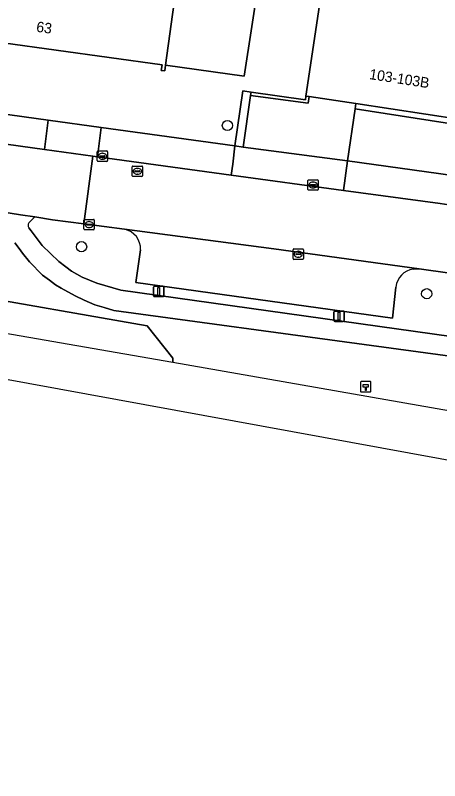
# Model space of a CAD drawing. Extents: x 163008 to 163854, y 382777 to 383982.
# Drawn here: x 163332.7 to 163373.4, y 382797.9 to 382871.4 of the extents above; entities that cross this region are included whole.
import ezdxf

# ---------------------------------------------------------------- set-up
doc = ezdxf.new("R2010")
doc.units = 0
for name, color, linetype in [('IMGEO_Boom', 7, 'Continuous'), ('IMGEO_Erf', 7, 'Continuous'), ('IMGEO_Fietspad_open', 7, 'Continuous'), ('IMGEO_Groenvoorziening', 7, 'Continuous'), ('IMGEO_Hectometerpaal', 7, 'Continuous'), ('IMGEO_Hek', 7, 'Continuous'), ('IMGEO_Kolk', 7, 'Continuous'), ('IMGEO_Lichtmast', 7, 'Continuous'), ('IMGEO_Muur', 7, 'Continuous'), ('IMGEO_Pand', 7, 'Continuous'), ('IMGEO_Pand_nummerreeks', 7, 'Continuous'), ('IMGEO_Parkeervlak_gesloten', 7, 'Continuous'), ('IMGEO_Parkeervlak_open', 7, 'Continuous'), ('IMGEO_Rijbaan_lokaal_open', 7, 'Continuous'), ('IMGEO_Rioolput', 7, 'Continuous'), ('IMGEO_Voetpad_gesloten', 7, 'Continuous'), ('IMGEO_Voetpad_open', 7, 'Continuous'), ('IMGEO_Waterloop', 7, 'Continuous')]:
    doc.layers.add(name, color=color, linetype=linetype)

msp = doc.modelspace()

# ---------------------------------------------------------------- linework, layer by layer
at = {"layer": 'IMGEO_Boom'}
for centre in [(163353.055, 382860.785), (163339.071, 382849.16), (163372.178, 382844.649)]:
    msp.add_circle(centre, 0.489, dxfattribs=at)
at = {"layer": 'IMGEO_Erf'}
for points in [[(163280.455, 382868.905), (163293.729, 382867.082), (163293.904, 382867.058), (163299.016, 382866.356), (163304.629, 382865.585), (163304.8, 382865.562), (163309.55, 382864.924), (163309.567, 382864.922), (163315.361, 382864.096), (163321.573, 382863.211), (163323.643, 382862.998), (163335.871, 382861.306), (163340.951, 382860.603), (163353.778, 382858.828), (163354.529, 382864.119), (163355.327, 382864.004), (163360.543, 382863.256), (163360.594, 382863.613), (163363.598, 382883.652)], [(163356.747, 382879.026), (163354.664, 382865.532), (163347.125, 382866.569), (163347.05, 382866.025), (163346.714, 382866.071), (163346.788, 382866.615), (163331.531, 382868.713), (163331.457, 382868.17), (163331.2, 382868.206), (163331.274, 382868.749), (163326.726, 382869.374), (163326.785, 382869.801), (163322.327, 382870.414), (163322.268, 382869.988), (163322.054, 382868.433), (163295.362, 382872.104)]]:
    msp.add_lwpolyline(points, dxfattribs=at)
at = {"layer": 'IMGEO_Fietspad_open'}
for points in [[(163333.993, 382851.453), (163334.575, 382852.01), (163333.199, 382852.227), (163329.807, 382852.762)], [(163499.251, 382822.021), (163494.803, 382822.681), (163390.478, 382838.302), (163342.832, 382844.985), (163340.526, 382845.669), (163339.133, 382846.245), (163338.098, 382846.827), (163337.562, 382847.213), (163336.875, 382847.731), (163335.282, 382849.281), (163334.239, 382850.672), (163334.016, 382850.97)], [(163332.653, 382849.515), (163333.07, 382848.976), (163333.412, 382848.539), (163334.065, 382847.703), (163335.332, 382846.43), (163335.997, 382845.943), (163336.58, 382845.516), (163337.125, 382845.189), (163338.464, 382844.438), (163339.318, 382844.032), (163340.356, 382843.584), (163341.233, 382843.336), (163342.164, 382843.039), (163390.211, 382836.499), (163442.533, 382828.767)]]:
    msp.add_lwpolyline(points, dxfattribs=at)
msp.add_arc((163334.367, 382851.229), 0.436, 149.04306, 216.40956, dxfattribs=at)
at = {"layer": 'IMGEO_Groenvoorziening'}
msp.add_lwpolyline([(163340.951, 382860.603), (163335.871, 382861.306), (163335.505, 382858.5), (163340.163, 382857.854), (163340.612, 382857.792)], close=True, dxfattribs=at)
for points in [[(163343.2, 382850.835), (163339.297, 382851.346), (163336.294, 382851.738), (163334.575, 382852.01), (163333.993, 382851.453)], [(163334.016, 382850.97), (163334.239, 382850.672), (163335.282, 382849.281), (163336.875, 382847.731), (163337.562, 382847.213), (163338.098, 382846.827), (163339.133, 382846.245), (163340.526, 382845.669), (163342.832, 382844.985), (163390.478, 382838.302), (163494.803, 382822.681), (163499.251, 382822.021)], [(163442.533, 382828.767), (163390.211, 382836.499), (163342.164, 382843.039), (163341.233, 382843.336), (163340.356, 382843.584), (163339.318, 382844.032), (163338.464, 382844.438), (163337.125, 382845.189), (163336.58, 382845.516), (163335.997, 382845.943), (163335.332, 382846.43), (163334.065, 382847.703), (163333.412, 382848.539), (163333.07, 382848.976), (163332.653, 382849.515)], [(163369.23, 382845.292), (163368.886, 382842.312), (163344.285, 382845.732), (163344.737, 382848.861)], [(163374.384, 382846.613), (163371.466, 382847.039), (163370.881, 382847.001)], [(163327.083, 382844.752), (163345.365, 382841.56), (163347.815, 382838.449), (163347.839, 382838.095), (163407.316, 382827.646), (163421.963, 382825.134)]]:
    msp.add_lwpolyline(points, dxfattribs=at)
for centre, radius, start, end in [((163334.367, 382851.229), 0.436, 149.04306, 216.40956), ((163342.772, 382848.916), 1.966, 358.39274, 77.41749), ((163371.143, 382845.096), 1.923, 97.83478, 174.14309)]:
    msp.add_arc(centre, radius, start, end, dxfattribs=at)
at = {"layer": 'IMGEO_Hectometerpaal'}
for p, q in [((163365.831, 382836.142), (163365.831, 382835.301)), ((163365.831, 382836.142), (163365.831, 382835.301)), ((163366.747, 382836.226), (163365.906, 382836.226)), ((163366.747, 382836.226), (163365.906, 382836.226)), ((163366.831, 382835.31), (163366.831, 382836.151)), ((163366.831, 382835.31), (163366.831, 382836.151)), ((163365.915, 382835.226), (163366.756, 382835.226)), ((163365.915, 382835.226), (163366.756, 382835.226))]:
    msp.add_line(p, q, dxfattribs=at)
msp.add_lwpolyline([(163366.356, 382835.37), (163366.296, 382835.37), (163366.296, 382835.675), (163366.076, 382835.675), (163366.076, 382835.944), (163366.576, 382835.944), (163366.576, 382835.675), (163366.356, 382835.675), (163366.356, 382835.37)], dxfattribs=at)
for centre, start, end in [((163365.909, 382836.148), 92.4484, 184.28452), ((163365.909, 382836.148), 92.4484, 184.28452), ((163366.753, 382836.148), 2.4484, 94.28452), ((163366.753, 382836.148), 2.4484, 94.28452), ((163366.753, 382835.304), 272.4484, 4.28452), ((163366.753, 382835.304), 272.4484, 4.28452), ((163365.909, 382835.304), 182.4484, 274.28452), ((163365.909, 382835.304), 182.4484, 274.28452)]:
    msp.add_arc(centre, 0.0779, start, end, dxfattribs=at)
at = {"layer": 'IMGEO_Hek'}
for points in [[(163353.778, 382858.828), (163354.529, 382864.119)], [(163354.529, 382864.119), (163355.327, 382864.004)]]:
    msp.add_lwpolyline(points, dxfattribs=at)
at = {"layer": 'IMGEO_Kolk'}
for p, q in [((163340.565, 382857.417), (163340.565, 382858.269)), ((163340.64, 382858.343), (163341.492, 382858.343)), ((163341.053, 382858.123), (163341.078, 382858.123)), ((163341.566, 382858.269), (163341.566, 382857.417)), ((163341.492, 382857.343), (163340.64, 382857.343)), ((163340.824, 382857.837), (163340.824, 382857.849)), ((163341.262, 382857.8), (163340.864, 382857.8)), ((163340.867, 382857.886), (163341.265, 382857.886)), ((163341.076, 382857.563), (163341.051, 382857.563)), ((163341.308, 382857.849), (163341.308, 382857.837)), ((163360.774, 382854.653), (163360.774, 382855.505)), ((163360.849, 382855.579), (163361.701, 382855.579)), ((163361.262, 382855.359), (163361.287, 382855.359)), ((163361.775, 382855.505), (163361.775, 382854.653)), ((163361.701, 382854.579), (163360.849, 382854.579)), ((163361.033, 382855.073), (163361.033, 382855.085)), ((163361.471, 382855.036), (163361.073, 382855.036)), ((163361.076, 382855.122), (163361.474, 382855.122)), ((163361.285, 382854.799), (163361.26, 382854.799)), ((163361.517, 382855.085), (163361.517, 382855.073)), ((163339.29, 382850.858), (163339.29, 382851.71)), ((163339.365, 382851.784), (163340.217, 382851.784)), ((163339.778, 382851.564), (163339.803, 382851.564)), ((163340.291, 382851.71), (163340.291, 382850.858)), ((163340.217, 382850.784), (163339.365, 382850.784)), ((163339.549, 382851.278), (163339.549, 382851.29)), ((163339.987, 382851.241), (163339.589, 382851.241)), ((163339.592, 382851.327), (163339.99, 382851.327)), ((163339.801, 382851.004), (163339.776, 382851.004)), ((163340.033, 382851.29), (163340.033, 382851.278)), ((163359.355, 382848.013), (163359.355, 382848.865)), ((163359.43, 382848.939), (163360.282, 382848.939)), ((163359.843, 382848.719), (163359.868, 382848.719)), ((163360.356, 382848.865), (163360.356, 382848.013)), ((163360.282, 382847.939), (163359.43, 382847.939)), ((163359.614, 382848.433), (163359.614, 382848.445)), ((163360.052, 382848.396), (163359.654, 382848.396)), ((163359.657, 382848.482), (163360.055, 382848.482)), ((163359.866, 382848.159), (163359.841, 382848.159)), ((163360.098, 382848.445), (163360.098, 382848.433))]:
    msp.add_line(p, q, dxfattribs=at)
for points in [[(163340.565, 382857.417), (163340.565, 382858.269)], [(163340.64, 382858.343), (163341.492, 382858.343)], [(163341.566, 382858.269), (163341.566, 382857.417)], [(163341.492, 382857.343), (163340.64, 382857.343)], [(163360.774, 382854.653), (163360.774, 382855.505)], [(163360.849, 382855.579), (163361.701, 382855.579)], [(163361.775, 382855.505), (163361.775, 382854.653)], [(163361.701, 382854.579), (163360.849, 382854.579)], [(163339.29, 382850.858), (163339.29, 382851.71)], [(163339.365, 382851.784), (163340.217, 382851.784)], [(163340.291, 382851.71), (163340.291, 382850.858)], [(163340.217, 382850.784), (163339.365, 382850.784)], [(163359.355, 382848.013), (163359.355, 382848.865)], [(163359.43, 382848.939), (163360.282, 382848.939)], [(163360.356, 382848.865), (163360.356, 382848.013)], [(163360.282, 382847.939), (163359.43, 382847.939)]]:
    msp.add_lwpolyline(points, dxfattribs=at)
for centre, radius, start, end in [((163340.642, 382858.267), 0.0765, 91.55205, 178.44795), ((163340.642, 382858.267), 0.0765, 91.55205, 178.44795), ((163341.49, 382858.267), 0.0765, 1.55205, 88.44795), ((163341.49, 382858.267), 0.0765, 1.55205, 88.44795), ((163340.642, 382857.419), 0.0765, 181.55205, 268.44795), ((163340.642, 382857.419), 0.0765, 181.55205, 268.44795), ((163340.864, 382857.846), 0.0403, 85.87752, 175.75265), ((163340.861, 382857.836), 0.0366, 178.93798, 274.71019), ((163341.265, 382857.843), 0.043, 264.86636, 352.45326), ((163341.269, 382857.848), 0.0386, 1.73085, 96.63898), ((163341.49, 382857.419), 0.0765, 271.55205, 358.44795), ((163341.49, 382857.419), 0.0765, 271.55205, 358.44795), ((163360.851, 382855.503), 0.0765, 91.55205, 178.44795), ((163360.851, 382855.503), 0.0765, 91.55205, 178.44795), ((163361.699, 382855.503), 0.0765, 1.55205, 88.44795), ((163361.699, 382855.503), 0.0765, 1.55205, 88.44795), ((163360.851, 382854.655), 0.0765, 181.55205, 268.44795), ((163360.851, 382854.655), 0.0765, 181.55205, 268.44795), ((163361.073, 382855.082), 0.0403, 85.87752, 175.75265), ((163361.07, 382855.072), 0.0366, 178.93798, 274.71019), ((163361.474, 382855.079), 0.043, 264.86636, 352.45326), ((163361.478, 382855.084), 0.0386, 1.73085, 96.63898), ((163361.699, 382854.655), 0.0765, 271.55205, 358.44795), ((163361.699, 382854.655), 0.0765, 271.55205, 358.44795), ((163339.367, 382851.708), 0.0765, 91.55205, 178.44795), ((163339.367, 382851.708), 0.0765, 91.55205, 178.44795), ((163340.215, 382851.708), 0.0765, 1.55205, 88.44795), ((163340.215, 382851.708), 0.0765, 1.55205, 88.44795), ((163339.367, 382850.86), 0.0765, 181.55205, 268.44795), ((163339.367, 382850.86), 0.0765, 181.55205, 268.44795), ((163339.589, 382851.287), 0.0403, 85.87752, 175.75265), ((163339.586, 382851.277), 0.0366, 178.93798, 274.71019), ((163339.99, 382851.284), 0.043, 264.86636, 352.45326), ((163339.994, 382851.289), 0.0386, 1.73085, 96.63898), ((163340.215, 382850.86), 0.0765, 271.55205, 358.44795), ((163340.215, 382850.86), 0.0765, 271.55205, 358.44795), ((163359.432, 382848.863), 0.0765, 91.55205, 178.44795), ((163359.432, 382848.863), 0.0765, 91.55205, 178.44795), ((163360.28, 382848.863), 0.0765, 1.55205, 88.44795), ((163360.28, 382848.863), 0.0765, 1.55205, 88.44795), ((163359.432, 382848.015), 0.0765, 181.55205, 268.44795), ((163359.432, 382848.015), 0.0765, 181.55205, 268.44795), ((163359.654, 382848.442), 0.0403, 85.87752, 175.75265), ((163359.651, 382848.432), 0.0366, 178.93798, 274.71019), ((163360.055, 382848.439), 0.043, 264.86636, 352.45326), ((163360.059, 382848.444), 0.0386, 1.73085, 96.63898), ((163360.28, 382848.015), 0.0765, 271.55205, 358.44795), ((163360.28, 382848.015), 0.0765, 271.55205, 358.44795)]:
    msp.add_arc(centre, radius, start, end, dxfattribs=at)
for centre, major_axis, ratio, start_param, end_param in [((163341.052, 382857.843), (-0.387, 0.002), 0.722429, 4.712389, 7.853982), ((163341.077, 382857.843), (-0.39, 0.002), 0.717154, 1.570796, 4.712389), ((163361.261, 382855.079), (-0.387, 0.002), 0.722429, 4.712389, 7.853982), ((163361.286, 382855.079), (-0.39, 0.002), 0.717154, 1.570796, 4.712389), ((163339.777, 382851.284), (-0.387, 0.002), 0.722429, 4.712389, 7.853982), ((163339.802, 382851.284), (-0.39, 0.002), 0.717154, 1.570796, 4.712389), ((163359.842, 382848.439), (-0.387, 0.002), 0.722429, 4.712389, 7.853982), ((163359.867, 382848.439), (-0.39, 0.002), 0.717154, 1.570796, 4.712389)]:
    msp.add_ellipse(centre, major_axis=major_axis, ratio=ratio, start_param=start_param, end_param=end_param, dxfattribs=at)
at = {"layer": 'IMGEO_Lichtmast'}
for p, q in [((163345.974, 382844.467), (163345.974, 382845.267)), ((163345.974, 382845.267), (163345.974, 382844.467)), ((163346.074, 382845.367), (163346.864, 382845.367)), ((163346.864, 382845.367), (163346.074, 382845.367)), ((163346.964, 382845.267), (163346.964, 382844.467)), ((163346.964, 382844.467), (163346.964, 382845.267)), ((163346.864, 382844.367), (163346.074, 382844.367)), ((163346.074, 382844.367), (163346.864, 382844.367)), ((163363.279, 382842.088), (163363.279, 382842.888)), ((163363.279, 382842.888), (163363.279, 382842.088)), ((163363.379, 382842.988), (163364.169, 382842.988)), ((163364.169, 382842.988), (163363.379, 382842.988)), ((163364.269, 382842.888), (163364.269, 382842.088)), ((163364.269, 382842.088), (163364.269, 382842.888)), ((163364.169, 382841.988), (163363.379, 382841.988)), ((163363.379, 382841.988), (163364.169, 382841.988))]:
    msp.add_line(p, q, dxfattribs=at)
for points in [[(163346.394, 382845.242), (163346.544, 382845.242), (163346.544, 382844.492), (163346.394, 382844.492), (163346.394, 382845.242)], [(163363.699, 382842.863), (163363.849, 382842.863), (163363.849, 382842.113), (163363.699, 382842.113), (163363.699, 382842.863)]]:
    msp.add_lwpolyline(points, dxfattribs=at)
for centre, start, end in [((163346.074, 382845.267), 90, 180), ((163346.074, 382845.267), 90, 180), ((163346.864, 382845.267), 0, 90), ((163346.864, 382845.267), 360, 90), ((163346.074, 382844.467), 180, 270), ((163346.074, 382844.467), 180, 270), ((163346.864, 382844.467), 270, 0), ((163346.864, 382844.467), 270, 0), ((163363.379, 382842.888), 90, 180), ((163363.379, 382842.888), 90, 180), ((163364.169, 382842.888), 0, 90), ((163364.169, 382842.888), 360, 90), ((163363.379, 382842.088), 180, 270), ((163363.379, 382842.088), 180, 270), ((163364.169, 382842.088), 270, 0), ((163364.169, 382842.088), 270, 0)]:
    msp.add_arc(centre, 0.1, start, end, dxfattribs=at)
at = {"layer": 'IMGEO_Muur'}
msp.add_lwpolyline([(163360.594, 382863.613), (163360.543, 382863.256), (163355.327, 382864.004), (163355.278, 382863.668), (163360.796, 382862.924), (163360.906, 382863.566)], close=True, dxfattribs=at)
at = {"layer": 'IMGEO_Pand'}
for points in [[(163383.283, 382880.62), (163378.143, 382881.412), (163363.598, 382883.652), (163360.594, 382863.613), (163360.906, 382863.566), (163365.381, 382862.889), (163375.465, 382861.363), (163380.343, 382860.625)], [(163348.498, 382876.556), (163328.1, 382879.361), (163327.964, 382878.37), (163323.506, 382878.984), (163323.642, 382879.974), (163319.328, 382880.568), (163318.783, 382876.605), (163323.097, 382876.012), (163322.327, 382870.414), (163326.785, 382869.801), (163326.726, 382869.374), (163331.274, 382868.749), (163331.2, 382868.206), (163331.457, 382868.17), (163331.531, 382868.713), (163346.788, 382866.615), (163346.714, 382866.071), (163347.05, 382866.025), (163347.125, 382866.569)], [(163348.498, 382876.556), (163347.125, 382866.569), (163354.664, 382865.532), (163356.747, 382879.026), (163353.676, 382879.448), (163353.251, 382876.354), (163348.559, 382876.999)]]:
    msp.add_lwpolyline(points, close=True, dxfattribs=at)
at = {"layer": 'IMGEO_Parkeervlak_gesloten'}
for points in [[(163370.881, 382847.001), (163371.466, 382847.039), (163357.498, 382848.967), (163343.2, 382850.835)], [(163344.737, 382848.861), (163344.285, 382845.732), (163368.886, 382842.312), (163369.23, 382845.292)]]:
    msp.add_lwpolyline(points, dxfattribs=at)
for centre, radius, start, end in [((163342.772, 382848.916), 1.966, 358.39274, 77.41749), ((163371.143, 382845.096), 1.923, 97.83478, 174.14309)]:
    msp.add_arc(centre, radius, start, end, dxfattribs=at)
at = {"layer": 'IMGEO_Parkeervlak_open'}
for points in [[(163335.871, 382861.306), (163323.643, 382862.998), (163323.304, 382860.193), (163335.505, 382858.5)], [(163364.585, 382857.4), (163374.693, 382855.989), (163375.396, 382860.833), (163365.307, 382862.378)], [(163340.951, 382860.603), (163340.612, 382857.792), (163353.433, 382856.013), (163353.582, 382857.082), (163353.778, 382858.828)]]:
    msp.add_lwpolyline(points, close=True, dxfattribs=at)
at = {"layer": 'IMGEO_Rijbaan_lokaal_open'}
msp.add_lwpolyline([(163323.304, 382860.193), (163321.756, 382860.315), (163321.191, 382860.36), (163315.036, 382861.25), (163309.181, 382862.096), (163304.385, 382862.719), (163304.27, 382862.735), (163293.542, 382864.229), (163289.273, 382864.823), (163288.403, 382858.45), (163289.217, 382858.337), (163309.507, 382855.515), (163317.148, 382854.52), (163328.342, 382852.995), (163329.807, 382852.762), (163333.199, 382852.227), (163334.575, 382852.01), (163336.294, 382851.738), (163339.297, 382851.346), (163340.163, 382857.854), (163335.505, 382858.5)], close=True, dxfattribs=at)
msp.add_lwpolyline([(163410.595, 382848.011), (163403.756, 382849.032), (163395.203, 382850.251), (163385.222, 382851.628), (163382.195, 382852.056), (163374.305, 382853.173), (163373.479, 382853.29), (163364.208, 382854.552), (163353.433, 382856.013), (163340.612, 382857.792), (163340.163, 382857.854), (163339.297, 382851.346), (163343.2, 382850.835), (163357.498, 382848.967), (163371.466, 382847.039), (163374.384, 382846.613), (163388.181, 382844.71), (163391.374, 382844.318), (163404.854, 382842.266), (163408.344, 382841.741), (163409.555, 382841.555)], dxfattribs=at)
at = {"layer": 'IMGEO_Rioolput'}
for p, q in [((163343.92, 382855.973), (163343.92, 382856.825)), ((163343.995, 382856.899), (163344.847, 382856.899)), ((163344.408, 382856.679), (163344.433, 382856.679)), ((163344.921, 382856.825), (163344.921, 382855.973)), ((163344.847, 382855.899), (163343.995, 382855.899)), ((163344.179, 382856.393), (163344.179, 382856.405)), ((163344.617, 382856.356), (163344.219, 382856.356)), ((163344.222, 382856.442), (163344.62, 382856.442)), ((163344.431, 382856.119), (163344.406, 382856.119)), ((163344.663, 382856.405), (163344.663, 382856.393))]:
    msp.add_line(p, q, dxfattribs=at)
for points in [[(163343.92, 382855.973), (163343.92, 382856.825)], [(163343.995, 382856.899), (163344.847, 382856.899)], [(163344.921, 382856.825), (163344.921, 382855.973)], [(163344.847, 382855.899), (163343.995, 382855.899)]]:
    msp.add_lwpolyline(points, dxfattribs=at)
for centre, radius, start, end in [((163343.997, 382856.823), 0.0765, 91.55205, 178.44795), ((163343.997, 382856.823), 0.0765, 91.55205, 178.44795), ((163344.845, 382856.823), 0.0765, 1.55205, 88.44795), ((163344.845, 382856.823), 0.0765, 1.55205, 88.44795), ((163343.997, 382855.975), 0.0765, 181.55205, 268.44795), ((163343.997, 382855.975), 0.0765, 181.55205, 268.44795), ((163344.219, 382856.402), 0.0403, 85.87752, 175.75265), ((163344.216, 382856.392), 0.0366, 178.93798, 274.71019), ((163344.62, 382856.399), 0.043, 264.86636, 352.45326), ((163344.624, 382856.404), 0.0386, 1.73085, 96.63898), ((163344.845, 382855.975), 0.0765, 271.55205, 358.44795), ((163344.845, 382855.975), 0.0765, 271.55205, 358.44795)]:
    msp.add_arc(centre, radius, start, end, dxfattribs=at)
for centre, major_axis, ratio, start_param, end_param in [((163344.407, 382856.399), (-0.387, 0.002), 0.722429, 4.712389, 7.853982), ((163344.432, 382856.399), (-0.39, 0.002), 0.717154, 1.570796, 4.712389)]:
    msp.add_ellipse(centre, major_axis=major_axis, ratio=ratio, start_param=start_param, end_param=end_param, dxfattribs=at)
at = {"layer": 'IMGEO_Voetpad_gesloten'}
msp.add_lwpolyline([(163315.914, 382846.807), (163315.893, 382846.691), (163315.348, 382843.727), (163316.289, 382843.564), (163347.839, 382838.095), (163347.815, 382838.449), (163345.365, 382841.56), (163327.083, 382844.752)], close=True, dxfattribs=at)
at = {"layer": 'IMGEO_Voetpad_open'}
for points in [[(163354.529, 382864.119), (163353.778, 382858.828), (163354.56, 382858.724), (163355.278, 382863.668), (163355.327, 382864.004)], [(163364.585, 382857.4), (163365.307, 382862.378), (163365.381, 382862.889), (163360.906, 382863.566), (163360.796, 382862.924), (163355.278, 382863.668), (163354.56, 382858.724)], [(163365.381, 382862.889), (163365.307, 382862.378), (163375.396, 382860.833), (163375.465, 382861.363)], [(163353.778, 382858.828), (163353.582, 382857.082), (163353.433, 382856.013), (163364.208, 382854.552), (163364.585, 382857.4), (163354.56, 382858.724)], [(163374.305, 382853.173), (163374.693, 382855.989), (163364.585, 382857.4), (163364.208, 382854.552), (163373.479, 382853.29)]]:
    msp.add_lwpolyline(points, close=True, dxfattribs=at)
at = {"layer": 'IMGEO_Waterloop'}
for points in [[(163542.415, 382797.919), (163125.436, 382874.202)], [(163209.827, 382871.108), (163252.738, 382861.689), (163258.496, 382858.498), (163259.917, 382858.193), (163280.241, 382852.682), (163286.764, 382850.914), (163308.109, 382845.126), (163308.262, 382844.467), (163308.481, 382844.431), (163312.853, 382843.711), (163313.212, 382844.062), (163315.348, 382843.727), (163316.289, 382843.564), (163347.839, 382838.095), (163407.316, 382827.646), (163421.963, 382825.134)]]:
    msp.add_lwpolyline(points, dxfattribs=at)

# ---------------------------------------------------------------- texts
at = {"layer": 'IMGEO_Pand_nummerreeks'}
for s, rotation, p in [('63', 352.16767, (163334.68, 382869.794)), ('103-103B', 351.22802, (163366.623, 382865.25))]:
    msp.add_text(s, height=1, rotation=rotation, dxfattribs=at).set_placement(p)

doc.saveas('drawing.dxf')
